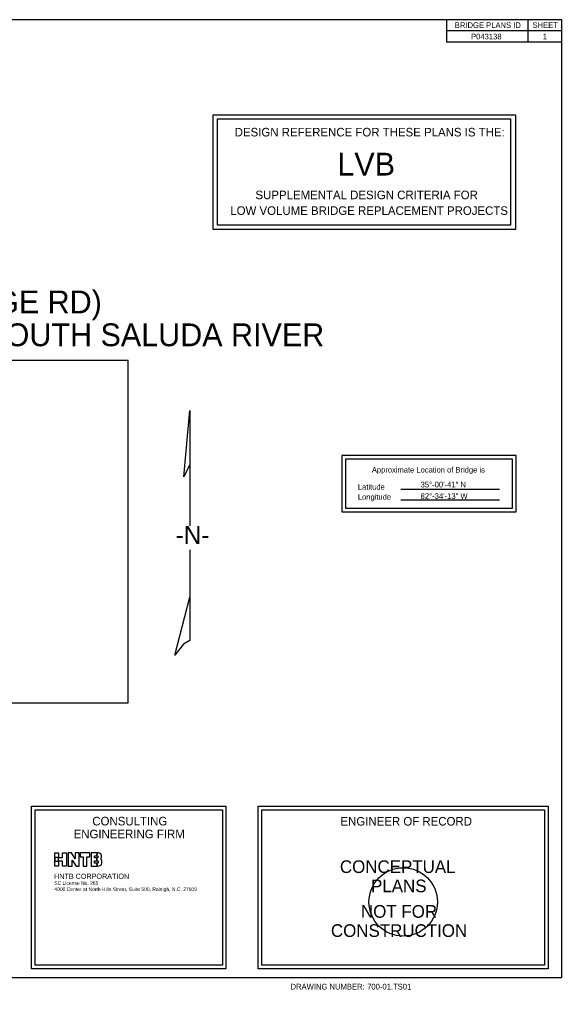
# Model space of a CAD drawing. Extents: x 0 to 4.15, y -2.5 to 1.79.
# Drawn here: x 1.801 to 2.792, y 0.02 to 1.792 of the extents above; entities that cross this region are included whole.
import ezdxf

# ---------------------------------------------------------------- set-up
doc = ezdxf.new("R2010")
doc.units = 0
for name, color, linetype in [('BR_AUTO DIMENSION', 7, 'Continuous'), ('BR_BORDER LINES', 7, 'Continuous'), ('BR_DETAILS', 7, 'Continuous'), ('BR_TEXT', 7, 'Continuous'), ('Default', 7, 'Continuous'), ('NoPlot', 7, 'Continuous'), ('V7_23', 7, 'Continuous')]:
    doc.layers.add(name, color=color, linetype=linetype)

msp = doc.modelspace()

# ---------------------------------------------------------------- linework, layer by layer
at = {"layer": 'BR_AUTO DIMENSION'}
for points in [[(2.1545, 1.4087), (2.7083, 1.4087), (2.7083, 1.6171), (2.1545, 1.6171)], [(2.1623, 1.4165), (2.6989, 1.4165), (2.6989, 1.6093), (2.1623, 1.6093)]]:
    msp.add_lwpolyline(points, close=True, dxfattribs=at)
at = {"layer": 'BR_BORDER LINES'}
for p, q in [((2.5815, 1.7917), (2.5815, 1.75)), ((2.73, 1.7917), (2.73, 1.75)), ((2.7917, 1.7708), (2.5815, 1.7708)), ((2.7917, 1.75), (2.5815, 1.75))]:
    msp.add_line(p, q, dxfattribs=at)
for points in [[(0.1667, 1.7917), (2.7917, 1.7917), (2.7917, 0.0417), (0.1667, 0.0417)], [(0.9583, 0.5438), (2, 0.5438), (2, 1.1688), (0.9583, 1.1688)], [(0.9583, 0.5438), (2, 0.5438), (2, 1.1688), (0.9583, 1.1688)]]:
    msp.add_lwpolyline(points, close=True, dxfattribs=at)
at = {"layer": 'BR_DETAILS'}
for p, q in [((2.4982, 0.9337), (2.6784, 0.9337)), ((2.4982, 0.9144), (2.6784, 0.9144)), ((1.8232, 0.3551), (2.1782, 0.3551)), ((1.8232, 0.0584), (1.8232, 0.3551)), ((2.1782, 0.3551), (2.1782, 0.0584)), ((1.8296, 0.3487), (2.1718, 0.3487)), ((1.8296, 0.0648), (1.8296, 0.3487)), ((2.1718, 0.3487), (2.1718, 0.0648)), ((2.1782, 0.0584), (1.8232, 0.0584)), ((2.1718, 0.0648), (1.8296, 0.0648))]:
    msp.add_line(p, q, dxfattribs=at)
for points in [[(2.7084, 0.9954), (2.39, 0.9954), (2.39, 0.8927), (2.7084, 0.8927)], [(2.7017, 0.9887), (2.3966, 0.9887), (2.3966, 0.8994), (2.7017, 0.8994)], [(2.2372, 0.3551), (2.7672, 0.3551), (2.7672, 0.0584), (2.2372, 0.0584)], [(2.2439, 0.3485), (2.7606, 0.3485), (2.7606, 0.0651), (2.2439, 0.0651)]]:
    msp.add_lwpolyline(points, close=True, dxfattribs=at)
at = {"layer": 'Default'}
for p, q in [((2.1013, 0.9564), (2.1124, 1.0778)), ((2.1124, 1.0778), (2.1124, 0.979)), ((2.1124, 0.979), (2.1013, 0.9564)), ((2.1124, 0.979), (2.1124, 0.9105)), ((2.1124, 0.9105), (2.1124, 0.8668)), ((2.1124, 0.8232), (2.1124, 0.7369)), ((2.0849, 0.6311), (2.1124, 0.7369)), ((2.1124, 0.7369), (2.1124, 0.7238)), ((2.1124, 0.7238), (2.1124, 0.6577))]:
    msp.add_line(p, q, dxfattribs=at)
msp.add_lwpolyline([(2.1124, 0.6577), (2.1006, 0.6512), (2.0849, 0.6311)], dxfattribs=at)
at = {"layer": 'NoPlot'}
msp.add_line((2.5022, 0.1804), (2.5022, 0.1804), dxfattribs=at)
msp.add_circle((2.5022, 0.1804), 0.0625, dxfattribs=at)
at = {"layer": 'V7_23'}
for p, q in [((1.8655, 0.2458), (1.8655, 0.2698)), ((1.8655, 0.2698), (1.8726, 0.2698)), ((1.8726, 0.2698), (1.8726, 0.2617)), ((1.8797, 0.2617), (1.8797, 0.2698)), ((1.8797, 0.2698), (1.8868, 0.2698)), ((1.8868, 0.2698), (1.8868, 0.2458)), ((1.8959, 0.2698), (1.8901, 0.2698)), ((1.8901, 0.2698), (1.8901, 0.2458)), ((1.903, 0.2593), (1.8959, 0.2698)), ((1.91, 0.2698), (1.903, 0.2698)), ((1.903, 0.2698), (1.903, 0.2593)), ((1.91, 0.2458), (1.91, 0.2698)), ((1.912, 0.2698), (1.912, 0.2629)), ((1.9297, 0.2698), (1.912, 0.2698)), ((1.9297, 0.2629), (1.9297, 0.2698)), ((1.9429, 0.2698), (1.9318, 0.2698)), ((1.9318, 0.2698), (1.9318, 0.2458)), ((1.9425, 0.2645), (1.9429, 0.2698)), ((1.9429, 0.2698), (1.9425, 0.2645)), ((1.8726, 0.2617), (1.8658, 0.2617)), ((1.8658, 0.2617), (1.8658, 0.2546)), ((1.8658, 0.2546), (1.8726, 0.2546)), ((1.8726, 0.2546), (1.8726, 0.2617)), ((1.8726, 0.2617), (1.8797, 0.2617)), ((1.8797, 0.2546), (1.8726, 0.2546)), ((1.8726, 0.2546), (1.8726, 0.2458)), ((1.8797, 0.2458), (1.8797, 0.2546)), ((1.8971, 0.2458), (1.8971, 0.2566)), ((1.8971, 0.2566), (1.9044, 0.2458)), ((1.912, 0.2629), (1.9173, 0.2629)), ((1.9173, 0.2629), (1.9173, 0.2458)), ((1.9244, 0.2458), (1.9244, 0.2629)), ((1.9244, 0.2629), (1.9297, 0.2629)), ((1.9384, 0.2609), (1.9384, 0.2645)), ((1.9384, 0.2645), (1.9425, 0.2645)), ((1.9427, 0.2609), (1.9384, 0.2609)), ((1.9384, 0.2512), (1.9384, 0.2556)), ((1.9384, 0.2556), (1.9424, 0.2556)), ((1.9425, 0.2512), (1.9384, 0.2512)), ((1.9424, 0.2556), (1.9427, 0.2609)), ((1.9427, 0.2609), (1.9424, 0.2556)), ((1.9428, 0.2458), (1.9425, 0.2512)), ((1.9425, 0.2512), (1.9428, 0.2458)), ((1.8726, 0.2458), (1.8655, 0.2458)), ((1.8868, 0.2458), (1.8797, 0.2458)), ((1.8901, 0.2458), (1.8971, 0.2458)), ((1.9044, 0.2458), (1.91, 0.2458)), ((1.9173, 0.2458), (1.9244, 0.2458)), ((1.9318, 0.2458), (1.9428, 0.2458))]:
    msp.add_line(p, q, dxfattribs=at)
for points in [[(1.9491, 0.2588), (1.9504, 0.2599), (1.951, 0.2616), (1.951, 0.2628), (1.951, 0.2671), (1.9479, 0.2698), (1.9429, 0.2698), (1.9429, 0.2698), (1.9429, 0.2698), (1.9429, 0.2698)], [(1.9424, 0.2556), (1.9446, 0.2556), (1.945, 0.2544), (1.945, 0.2534), (1.945, 0.252), (1.9441, 0.2512), (1.9425, 0.2512)], [(1.9425, 0.2645), (1.9444, 0.2645), (1.9446, 0.2632), (1.9446, 0.2627), (1.9446, 0.2621), (1.9442, 0.2609), (1.9427, 0.2609)], [(1.9428, 0.2458), (1.9483, 0.2458), (1.9517, 0.2489), (1.9517, 0.2539), (1.9517, 0.2558), (1.9507, 0.2577), (1.9491, 0.2588)]]:
    msp.add_open_spline(points, degree=3, dxfattribs=at)

# ---------------------------------------------------------------- texts
at = {"layer": 'BR_AUTO DIMENSION'}
for s, p in [('35°-00\'-41" N', (2.534, 0.9372)), ('82°-34\'-13" W', (2.534, 0.9162))]:
    msp.add_text(s, height=0.010417, dxfattribs=at).set_placement(p)
at = {"layer": 'BR_DETAILS'}
for s, p in [('Approximate Location of Bridge is', (2.445, 0.9644)), ('Latitude', (2.4194, 0.9331)), ('Longitude', (2.4194, 0.9148))]:
    msp.add_text(s, height=0.01, dxfattribs=at).set_placement(p)
for s, height, p in [('CONCEPTUAL', 0.02311, (2.3866, 0.2332)), ('PLANS', 0.02311, (2.4435, 0.1981)), ('NOT FOR', 0.02311, (2.4251, 0.1515)), ('CONSTRUCTION', 0.023108, (2.3702, 0.1165))]:
    msp.add_text(s, height=height, rotation=360, dxfattribs=at).set_placement(p)
at = {"layer": 'BR_TEXT'}
for s, height, p in [('CONSULTING', 0.01563, (1.9342, 0.3201)), ('ENGINEERING FIRM', 0.015625, (1.9, 0.2966))]:
    msp.add_text(s, height=height, rotation=0, dxfattribs=at).set_placement(p)
for s, height, p in [('HNTB CORPORATION', 0.009516, (1.8643, 0.2225)), ('SC License No. 265', 0.006558, (1.8647, 0.2115)), ('4000 Center at North Hills Street, Suite 500, Raleigh, N.C. 27609', 0.006558, (1.8647, 0.2004))]:
    msp.add_text(s, height=height, dxfattribs=at).set_placement(p)
at = {"layer": 'Default'}
for s, height, p in [('BRIDGE PLANS ID', 0.010417, (2.5965, 1.776)), ('SHEET', 0.01042, (2.7385, 1.776)), ('P043138', 0.01042, (2.6262, 1.7552)), ('1', 0.0104, (2.7572, 1.7552)), ('DESIGN REFERENCE FOR THESE PLANS IS THE:', 0.015625, (2.1943, 1.578)), ('LVB', 0.04167, (2.382, 1.5066)), ('SUPPLEMENTAL DESIGN CRITERIA FOR', 0.015625, (2.2323, 1.4634)), ('LOW VOLUME BRIDGE REPLACEMENT PROJECTS', 0.015625, (2.1863, 1.4348)), ('ROUTE S-39-26 (PACE BRIDGE RD)', 0.041667, (1.0135, 1.255)), ('REPLACE BRIDGE OVER TRIBUTARY TO SOUTH SALUDA RIVER', 0.041667, (0.6365, 1.195)), ('-N-', 0.03333, (2.0864, 0.8337)), ('ENGINEER OF RECORD', 0.015625, (2.3876, 0.3198)), ('DRAWING NUMBER:', 0.010417, (2.2964, 0.0205)), ('700-01.TS01', 0.010417, (2.4364, 0.0205))]:
    msp.add_text(s, height=height, dxfattribs=at).set_placement(p)

doc.saveas('drawing.dxf')
